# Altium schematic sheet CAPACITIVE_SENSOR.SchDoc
size A
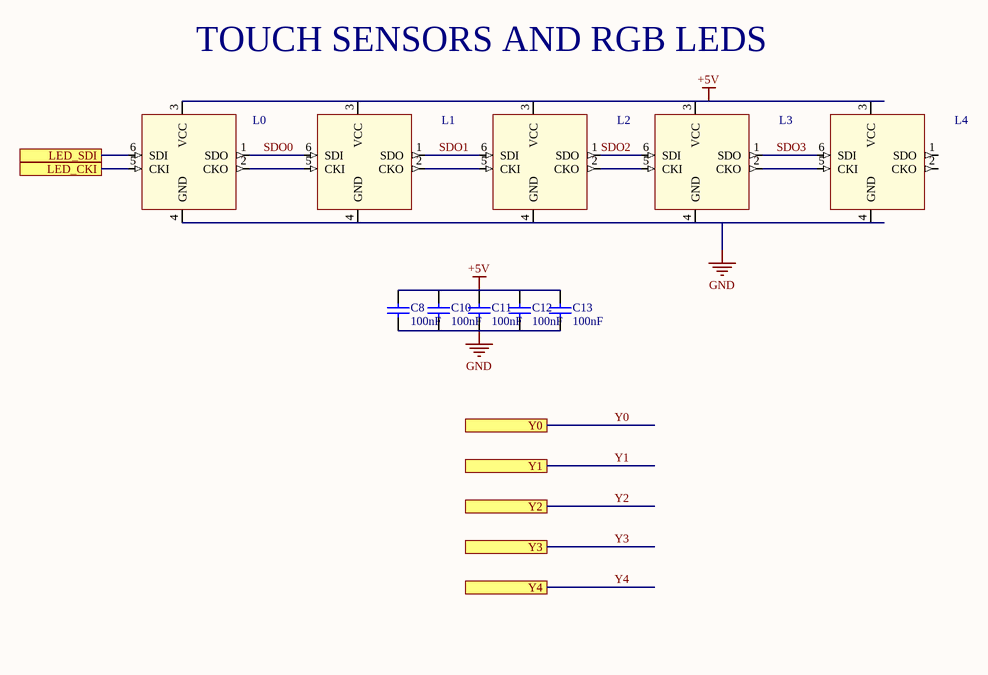
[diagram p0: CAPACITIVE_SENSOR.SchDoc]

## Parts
C8  value 100nF  [CAP-0402]  (hidden comment: C0402C104K3PACTU)
C10  value 100nF  [CAP-0402]  (hidden comment: C0402C104K3PACTU)
C11  value 100nF  [CAP-0402]  (hidden comment: C0402C104K3PACTU)
C12  value 100nF  [CAP-0402]  (hidden comment: C0402C104K3PACTU)
C13  value 100nF  [CAP-0402]  (hidden comment: C0402C104K3PACTU)
L0  APA1022020-2018  [APA102-2020-Footprint-1]  (value not drawn)
L1  APA1022020-2018  [APA102-2020-Footprint-1]  (value not drawn)
L2  APA1022020-2018  [APA102-2020-Footprint-1]  (value not drawn)
L3  APA1022020-2018  [APA102-2020-Footprint-1]  (value not drawn)
L4  APA1022020-2018  [APA102-2020-Footprint-1]  (value not drawn)

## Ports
LED_CKI, LED_SDI, Y0, Y1, Y2, Y3, Y4

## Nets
+5V: C8.2 C10.2 C11.2 C12.2 C13.2 L0.3(VCC) L1.3(VCC) L2.3(VCC) L3.3(VCC) L4.3(VCC)
GND: C8.1 C10.1 C11.1 C12.1 C13.1 L0.4(GND) L1.4(GND) L2.4(GND) L3.4(GND) L4.4(GND)
LED_CKI: L0.5(CKI) ; port LED_CKI
LED_SDI: L0.6(SDI) ; port LED_SDI
SDO0: L0.1(SDO) L1.6(SDI)
SDO1: L1.1(SDO) L2.6(SDI)
SDO2: L2.1(SDO) L3.6(SDI)
SDO3: L3.1(SDO) L4.6(SDI)
NetL0_2: L0.2(CKO) L1.5(CKI)
NetL1_2: L1.2(CKO) L2.5(CKI)
NetL2_2: L2.2(CKO) L3.5(CKI)
NetL3_2: L3.2(CKO) L4.5(CKI)

Not connected (* = marked no-connect by the designer): L4 1(SDO) 2(CKO)

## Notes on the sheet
- TOUCH SENSORS AND RGB LEDS

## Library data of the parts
C8 C10-C13 = C0014-A.3: CAP CHIP 0402 100nF 25V X5R 10%; Manufacturer: KEMET; Code Arduino: 0132
L0-L4 = L0003-A.7: LED RGB 2020; Manufacturer: Shenzhen LED Color Opto Electronic CO.,LTD.; Code Arduino: A5307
